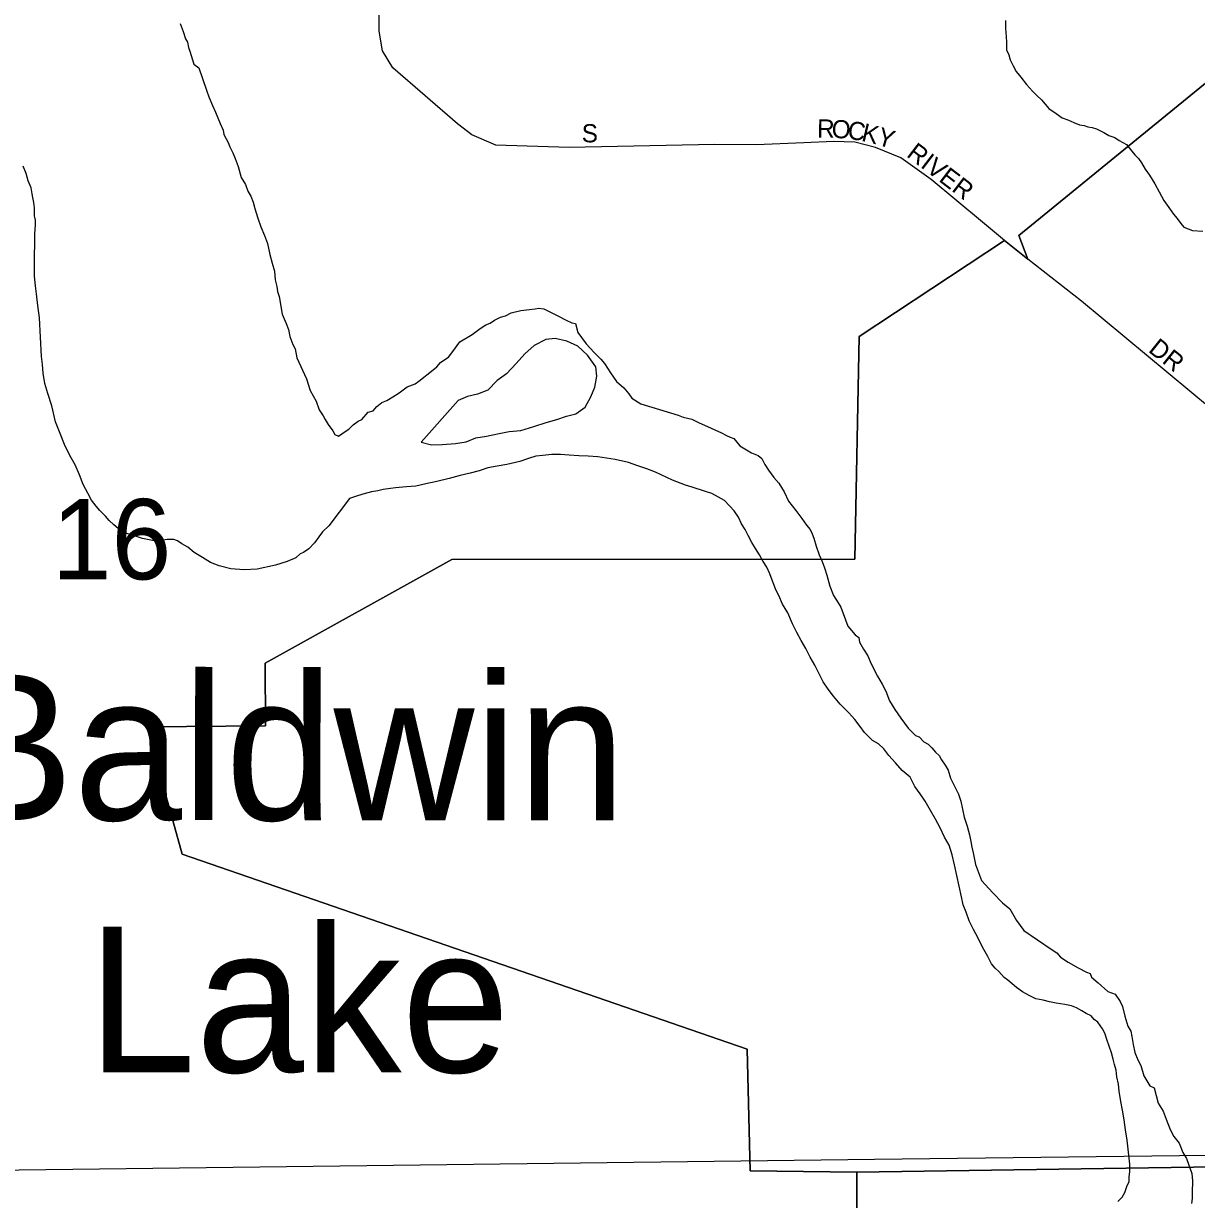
# Model space of a CAD drawing. Extents: x 2010165 to 2382125, y 1060529 to 1407316.
# Drawn here: x 2145137 to 2148360, y 1221171 to 1224404 of the extents above; entities that cross this region are included whole.
import ezdxf

# ---------------------------------------------------------------- set-up
doc = ezdxf.new("R2010")
doc.units = 0
for name, color, linetype in [('GM_X_City_Street', 7, 'Continuous'), ('GM_X_City_Street_Text', 7, 'Continuous'), ('GM_X_Corporation', 7, 'Continuous'), ('GM_X_Major_River', 7, 'Continuous'), ('GM_X_Minor_Lake_Text', 7, 'Continuous'), ('GM_X_Minor_River', 7, 'Continuous'), ('GM_X_Minor_River_Text', 7, 'Continuous'), ('GM_X_Section', 7, 'Continuous'), ('GM_X_Section_Text', 7, 'Continuous')]:
    doc.layers.add(name, color=color, linetype=linetype)

msp = doc.modelspace()

# ---------------------------------------------------------------- linework, layer by layer
at = {"layer": 'GM_X_City_Street'}
for points in [[(2147771.7, 1223857.6), (2147631.2, 1223974.9), (2147547.3, 1224035.1), (2147477.7, 1224063.5), (2147420.8, 1224077.8), (2147362.2, 1224079.3), (2147281.5, 1224076.2), (2147149.8, 1224070.3), (2147035.8, 1224071.2), (2146636, 1224063.5), (2146435, 1224069.9), (2146368.5, 1224098.3), (2146329, 1224128.4), (2146151.8, 1224281.9), (2146123.3, 1224329.3), (2146113.8, 1224383.1), (2146115.4, 1224800.9), (2146107.5, 1225125.2), (2146102.7, 1225683.8), (2146099.5, 1225758.1), (2146090.1, 1225826.2), (2146034.9, 1226118.8)], [(2148520, 1223244.9), (2148044.2, 1223641.1), (2147897, 1223756.5), (2147832.2, 1223807.2), (2147771.7, 1223857.6)]]:
    msp.add_lwpolyline(points, dxfattribs=at)
at = {"layer": 'GM_X_Corporation'}
for points in [[(2148518.6, 1224348.8), (2147871.9, 1223821.2), (2147897, 1223756.6), (2147832.2, 1223807.2), (2147433.5, 1223543.6), (2147420.8, 1222931.5), (2146313.5, 1222930.5), (2145801.1, 1222645.7), (2145801.8, 1222473.2), (2145475.4, 1222470.1), (2145572.8, 1222120.5), (2147124.9, 1221584.6), (2147133.9, 1221249.7), (2147426.3, 1221246.2), (2147423.5, 1218928.8)], [(2151804.7, 1221311.6), (2147426.3, 1221246.2), (2147133.9, 1221249.7), (2147124.9, 1221584.6), (2145572.8, 1222120.5), (2145475.4, 1222470.1), (2145801.8, 1222473.2), (2145801.1, 1222645.7), (2146313.5, 1222930.5), (2147420.8, 1222931.5), (2147433.5, 1223543.6), (2147832.2, 1223807.2), (2147897, 1223756.6), (2147871.9, 1223821.2), (2148518.6, 1224348.8)], [(2147423.5, 1218928.8), (2147426.3, 1221246.2), (2151804.7, 1221311.6), (2152701.8, 1221309.3), (2153236.4, 1221311.5), (2153786.8, 1221330), (2154189.1, 1221338.2), (2155059.4, 1221364.3), (2155838.4, 1221371.7), (2159035.7, 1221398.8), (2160539.4, 1221412.4), (2164895.8, 1221436.7), (2164832.8, 1218637)]]:
    msp.add_lwpolyline(points, dxfattribs=at)
at = {"layer": 'GM_X_Major_River'}
for points in [[(2145567, 1224404.4), (2145575.3, 1224382.4), (2145581.6, 1224362.4), (2145587.7, 1224352.5), (2145589.9, 1224338.4), (2145594.1, 1224328.5), (2145604.6, 1224292.5), (2145618.7, 1224282.6), (2145639.6, 1224220.7), (2145645.8, 1224202.7), (2145656.1, 1224178.7), (2145664.4, 1224160.8), (2145670.6, 1224144.8), (2145676.8, 1224128.8), (2145685.1, 1224110.9), (2145687.2, 1224098.9), (2145693.4, 1224086.9), (2145699.5, 1224076.9), (2145703.7, 1224064.9), (2145711.9, 1224049), (2145718.1, 1224033), (2145726.5, 1224011.1), (2145734.9, 1223981.1), (2145747.1, 1223961.1), (2145753.4, 1223943.2), (2145761.6, 1223929.2), (2145767.8, 1223913.2), (2145772, 1223895.2), (2145780.4, 1223869.3), (2145788.7, 1223845.3), (2145799.1, 1223821.3), (2145807.4, 1223799.4), (2145813.8, 1223769.3), (2145820.1, 1223745.3), (2145826.4, 1223723.3), (2145828.7, 1223699.3), (2145832.9, 1223681.3), (2145835.1, 1223667.3), (2145839.3, 1223653.3), (2145848, 1223605.2), (2145858.3, 1223579.3), (2145864.6, 1223563.3), (2145868.8, 1223543.3), (2145877.1, 1223521.3), (2145883.3, 1223509.3), (2145887.6, 1223485.3), (2145914.4, 1223427.5), (2145924.8, 1223395.5), (2145941.3, 1223365.6), (2145949.6, 1223341.6), (2145959.8, 1223325.7), (2145966, 1223315.7), (2145974.2, 1223301.8), (2145986.4, 1223283.9), (2145992.6, 1223273.9), (2146002.6, 1223270), (2146020.5, 1223282.3), (2146030.4, 1223288.4), (2146042.3, 1223300.6), (2146056.2, 1223310.8), (2146066.1, 1223315), (2146083.9, 1223335.2), (2146097.9, 1223339.4), (2146107.7, 1223351.6), (2146121.6, 1223361.8), (2146135.6, 1223368), (2146151.5, 1223378.2), (2146169.4, 1223388.5), (2146191.2, 1223404.8), (2146213.1, 1223413.1), (2146223, 1223421.2)], [(2145180.9, 1223595), (2145176.5, 1223629.1), (2145172.1, 1223661.1), (2145169.8, 1223683.2), (2145167.4, 1223709.2), (2145167, 1223739.3), (2145166.7, 1223767.4), (2145168.3, 1223797.5), (2145167.9, 1223825.6), (2145169.6, 1223849.7), (2145169.4, 1223863.8), (2145167.2, 1223875.8), (2145167.1, 1223887.8), (2145166.9, 1223897.8), (2145164.8, 1223911.9), (2145162.6, 1223925.9), (2145160.4, 1223935.9), (2145158.2, 1223951.9), (2145149.9, 1223971.9), (2145143.7, 1223991.9), (2145135.4, 1224011.8)], [(2146223, 1223421.2), (2146262.7, 1223451.8), (2146272.6, 1223460), (2146282.5, 1223472.1), (2146294.4, 1223480.3), (2146304.3, 1223486.4), (2146316.1, 1223502.6), (2146335.8, 1223528.9), (2146369.6, 1223549.4), (2146391.4, 1223565.8), (2146407.3, 1223576), (2146419.3, 1223580.1), (2146431.2, 1223588.3), (2146447.1, 1223596.5), (2146461.1, 1223600.7), (2146477, 1223608.9), (2146503, 1223615.3), (2146527, 1223617.6), (2146543, 1223619.8), (2146553, 1223621.9), (2146567, 1223620.1), (2146581.2, 1223612.2), (2146605.4, 1223600.5), (2146627.6, 1223588.7), (2146643.7, 1223580.9), (2146653.7, 1223579), (2146660.1, 1223555), (2146682.5, 1223523.2), (2146704.9, 1223499.4), (2146723.1, 1223481.5), (2146733.3, 1223469.6), (2146749.7, 1223443.7), (2146766, 1223419.9), (2146786.3, 1223402.1), (2146800.5, 1223386.2), (2146808.7, 1223374.2), (2146832.9, 1223358.5), (2146935.5, 1223327.6), (2146949.6, 1223321.8), (2146973.7, 1223316.1), (2146993.9, 1223306.3), (2147016.1, 1223296.5), (2147036.2, 1223286.7), (2147054.4, 1223278.9), (2147068.5, 1223271.1), (2147078.6, 1223267.2), (2147088.6, 1223263.3), (2147104.9, 1223243.4), (2147137.2, 1223223.8), (2147155.4, 1223216), (2147165.5, 1223208.1), (2147173.7, 1223192.1), (2147183.9, 1223176.2), (2147198.2, 1223156.3), (2147212.4, 1223140.4), (2147226.8, 1223116.5), (2147239.1, 1223090.6), (2147259.5, 1223064.8), (2147275.8, 1223042.9), (2147288.1, 1223025), (2147298.3, 1223013.1), (2147304.4, 1223001.1), (2147308.6, 1222989.1), (2147314.9, 1222967.1), (2147323.2, 1222943.1), (2147331.5, 1222925.2), (2147337.7, 1222907.2), (2147344, 1222887.2), (2147352.4, 1222857.2), (2147362.7, 1222831.3), (2147375, 1222811.3), (2147383.2, 1222799.4), (2147401.9, 1222747.5), (2147422.3, 1222723.6), (2147432.4, 1222715.7), (2147434.5, 1222703.7), (2147444.8, 1222683.8), (2147457.1, 1222665.9), (2147465.4, 1222645.9), (2147483.9, 1222610), (2147496.2, 1222588.1), (2147506.4, 1222568.2), (2147516.8, 1222542.2), (2147531.1, 1222518.3), (2147547.5, 1222494.4), (2147567.9, 1222466.6), (2147588.2, 1222446.8), (2147598.2, 1222442.9), (2147610.4, 1222429), (2147622.5, 1222423.1), (2147632.7, 1222413.2), (2147642.9, 1222401.3), (2147653, 1222391.4), (2147659.2, 1222379.4), (2147669.4, 1222365.5), (2147677.6, 1222351.6), (2147683.9, 1222329.6), (2147696.2, 1222305.6), (2147706.5, 1222285.7), (2147712.8, 1222265.7), (2147721.3, 1222221.7)], [(2147169.2, 1222925.2), (2147158.9, 1222943.1), (2147148.7, 1222961.1), (2147138.4, 1222977), (2147128.2, 1222996.9), (2147119.9, 1223012.9), (2147109.7, 1223028.8), (2147101.5, 1223046.8), (2147089.2, 1223064.7), (2147062.8, 1223092.4), (2147046.7, 1223102.3), (2147028.5, 1223112.1), (2147010.4, 1223117.9), (2146974.2, 1223129.5), (2146956.1, 1223135.3), (2146919.8, 1223148.9), (2146873.5, 1223170.4), (2146849.3, 1223180.1), (2146825.1, 1223187.8), (2146799, 1223197.6), (2146762.8, 1223205.1), (2146738.7, 1223208.8), (2146714.6, 1223212.6), (2146688.6, 1223214.2), (2146662.5, 1223215.9), (2146636.4, 1223217.6), (2146612.4, 1223219.3), (2146588.3, 1223219), (2146564.3, 1223216.7), (2146544.3, 1223214.5), (2146524.3, 1223208.2), (2146500.4, 1223199.9), (2146464.5, 1223191.4), (2146438.5, 1223187.1), (2146412.5, 1223182.8), (2146388.6, 1223174.4), (2146364.6, 1223168.1), (2146336.6, 1223161.8), (2146306.7, 1223153.4), (2146272.7, 1223144.9), (2146242.8, 1223138.6), (2146214.8, 1223132.2), (2146188.8, 1223129.9), (2146158.8, 1223127.5), (2146144.8, 1223125.3), (2146124.8, 1223123.1), (2146110.8, 1223118.9), (2146092.8, 1223116.6), (2146068.8, 1223110.3), (2146048.9, 1223104.1), (2146032.9, 1223097.8), (2145975.8, 1223022.9), (2145958, 1223006.6), (2145948.2, 1222992.5), (2145936.4, 1222976.3), (2145920.5, 1222960), (2145906.6, 1222949.8), (2145896.7, 1222945.7), (2145884.8, 1222935.5), (2145860.9, 1222925.2), (2145829, 1222914.8), (2145779, 1222904.1), (2145743, 1222901.7), (2145706.9, 1222905.2), (2145674.7, 1222912.9), (2145650.5, 1222922.6), (2145628.3, 1222936.4), (2145606.1, 1222950.1), (2145587.9, 1222964), (2145571.7, 1222973.8), (2145559.6, 1222981.7), (2145549.5, 1222985.6), (2145531.5, 1222985.3), (2145515.5, 1222983.1), (2145491.5, 1222982.9), (2145463.4, 1222988.5), (2145439.2, 1222996.3), (2145421.1, 1223002.1), (2145409, 1223007.9), (2145396.9, 1223015.8), (2145384.7, 1223025.7), (2145372.6, 1223037.6), (2145362.4, 1223049.5), (2145346.1, 1223065.3), (2145336, 1223077.3), (2145323.7, 1223093.2), (2145313.5, 1223113.1), (2145301.1, 1223137), (2145290.8, 1223163), (2145278.4, 1223190.9), (2145264, 1223216.8), (2145249.6, 1223246.8), (2145237.2, 1223276.7), (2145224.8, 1223308.6), (2145214.2, 1223352.7), (2145203.7, 1223386.6), (2145195.3, 1223414.6), (2145190.9, 1223442.7), (2145188.6, 1223466.7), (2145186.3, 1223488.8), (2145180.9, 1223595)], [(2146331, 1223367.9), (2146229.4, 1223253.3)], [(2148143.9, 1221165.4), (2148155.7, 1221177.6), (2148163.6, 1221189.8), (2148169.3, 1221209.9), (2148175.2, 1221220), (2148175.1, 1221232), (2148176.9, 1221248.1), (2148176.6, 1221268.2), (2148169.7, 1221334.3), (2148165.3, 1221362.3), (2148161, 1221390.4), (2148156.6, 1221416.4), (2148152.3, 1221440.4), (2148147.9, 1221468.5), (2148145.7, 1221488.5), (2148141.4, 1221508.5), (2148139.2, 1221526.6), (2148134.9, 1221542.6), (2148130.8, 1221556.5), (2148126.5, 1221574.5), (2148120.3, 1221592.5), (2148114, 1221610.5), (2148107.8, 1221628.5), (2148101.6, 1221640.5), (2148089.3, 1221658.4), (2148079.2, 1221666.3), (2148071.1, 1221676.2), (2148057, 1221682.1), (2148044.9, 1221689.9), (2148030.7, 1221697.8), (2148016.6, 1221703.6), (2147998.6, 1221707.4), (2147974.5, 1221711.1), (2147956.4, 1221714.9), (2147938.3, 1221718.7), (2147918.2, 1221722.5), (2147900.1, 1221732.3), (2147881.9, 1221742.1), (2147865.7, 1221753.9), (2147853.6, 1221763.8), (2147841.4, 1221773.7), (2147831.3, 1221781.6), (2147817.1, 1221797.5), (2147806.9, 1221807.4), (2147796.7, 1221819.3), (2147786.4, 1221839.2), (2147772.1, 1221865.1), (2147759.8, 1221889.1), (2147747.4, 1221913), (2147735.1, 1221936.9), (2147726.8, 1221960.9), (2147718.5, 1221980.9), (2147714.2, 1222002.9), (2147695, 1222090.9), (2147688.6, 1222118.9), (2147680.3, 1222144.9), (2147668, 1222166.8), (2147655.6, 1222192.8), (2147643.3, 1222216.7), (2147628.9, 1222240.6), (2147614.6, 1222266.5), (2147600.3, 1222286.4), (2147586, 1222306.3), (2147573.6, 1222332.2), (2147551.4, 1222350), (2147533.1, 1222371.9), (2147514.8, 1222391.7), (2147500.5, 1222409.6), (2147486.3, 1222423.5), (2147470.1, 1222433.3), (2147460, 1222443.2), (2147447.8, 1222455.1), (2147435.6, 1222471), (2147421.3, 1222490.9), (2147405, 1222508.7), (2147380.7, 1222532.5), (2147362.4, 1222554.4), (2147348.1, 1222574.3), (2147333.8, 1222594.1), (2147323.5, 1222616.1), (2147311.2, 1222640), (2147298.9, 1222661.9), (2147286.5, 1222685.9), (2147274.2, 1222707.8), (2147261.9, 1222729.7), (2147249.6, 1222753.6), (2147237.2, 1222783.6), (2147222.8, 1222807.5), (2147212.5, 1222831.4), (2147204.3, 1222847.4), (2147200.1, 1222857.4), (2147193.9, 1222873.3), (2147187.7, 1222891.3), (2147179.4, 1222909.3), (2147169.2, 1222925.2)], [(2147721.3, 1222221.7), (2147729.7, 1222197.7), (2147733.9, 1222183.7), (2147736, 1222173.7), (2147740.2, 1222155.7), (2147742.4, 1222139.7), (2147746.7, 1222123.7), (2147753.1, 1222091.6), (2147769.7, 1222047.7), (2147800.2, 1222014), (2147826.6, 1221986.2), (2147846.8, 1221970.4), (2147865.3, 1221938.5), (2147885.7, 1221910.7), (2147960.5, 1221859.4), (2147976.6, 1221849.6), (2147986.8, 1221837.7), (2148007, 1221823.9), (2148035.3, 1221808.2), (2148057.5, 1221796.4), (2148067.6, 1221792.5), (2148071.7, 1221782.5), (2148089.9, 1221766.7), (2148116.3, 1221743), (2148136.4, 1221735.2), (2148150.7, 1221715.3), (2148156.9, 1221701.3), (2148163.3, 1221675.3), (2148171.6, 1221647.3), (2148179.8, 1221633.4), (2148182, 1221619.4), (2148186.3, 1221597.3), (2148190.6, 1221575.3), (2148198.9, 1221555.4), (2148207.1, 1221539.4), (2148215.5, 1221511.4), (2148231.9, 1221483.5), (2148244, 1221477.7), (2148254.5, 1221435.7), (2148268.9, 1221413.8), (2148277.2, 1221391.8), (2148287.5, 1221363.8), (2148297.8, 1221343.9), (2148312.1, 1221326), (2148322.4, 1221300.1), (2148332.7, 1221284.1), (2148347.2, 1221242.2), (2148349.5, 1221222.1), (2148347.9, 1221190), (2148348.1, 1221174), (2148346.3, 1221159.9)]]:
    msp.add_lwpolyline(points, dxfattribs=at)
at = {"layer": 'GM_X_Minor_River'}
msp.add_lwpolyline([(2147834.9, 1224412.1), (2147835.2, 1224390.1), (2147837.5, 1224368), (2147837.7, 1224352), (2147838, 1224331.9), (2147844.2, 1224318), (2147848.4, 1224304), (2147856.6, 1224288), (2147864.8, 1224272.1), (2147877, 1224256.2), (2147893.3, 1224236.3), (2147909.6, 1224218.4), (2147921.8, 1224206.6), (2147933.9, 1224194.7), (2147944.1, 1224182.7), (2147954.3, 1224170.8), (2147974.5, 1224157), (2147990.7, 1224145.2), (2148006.8, 1224139.4), (2148022.9, 1224131.6), (2148039, 1224125.7), (2148051.1, 1224123.9), (2148061.1, 1224120), (2148073.2, 1224118.1), (2148085.2, 1224114.2), (2148105.4, 1224104.5), (2148119.5, 1224096.6), (2148135.6, 1224090.8), (2148147.8, 1224082.9), (2148157.9, 1224077), (2148168, 1224071.1), (2148182.2, 1224053.2), (2148190.4, 1224043.3), (2148200.5, 1224033.4), (2148208.7, 1224021.5), (2148218.9, 1224003.5), (2148231.2, 1223987.6), (2148245.5, 1223963.7), (2148257.8, 1223941.8), (2148270.1, 1223917.9), (2148284.4, 1223898), (2148296.7, 1223880.1), (2148306.9, 1223868.2), (2148317.1, 1223854.2), (2148325.2, 1223844.3), (2148349.4, 1223834.6), (2148377.4, 1223832.9)], dxfattribs=at)
at = {"layer": 'GM_X_Minor_River_Text'}
msp.add_lwpolyline([(2146229.4, 1223253.3), (2146257.6, 1223245.9), (2146287.6, 1223246.6), (2146323.7, 1223249.4), (2146353.6, 1223254), (2146379.4, 1223264.6), (2146409.4, 1223269.3), (2146439.3, 1223276), (2146471.2, 1223282.7), (2146503.2, 1223285.4), (2146539, 1223296.2), (2146572.8, 1223307), (2146602.7, 1223315.7), (2146628.6, 1223324.3), (2146654.5, 1223330.8), (2146680.1, 1223349.5), (2146695.5, 1223377.9), (2146706.9, 1223404.2), (2146712.3, 1223434.4), (2146709.7, 1223460.5), (2146686.9, 1223492.1), (2146660.3, 1223517.5), (2146629.9, 1223530.9), (2146597.7, 1223538.2), (2146571.7, 1223535.7), (2146540, 1223518.9), (2146514.5, 1223496.3), (2146491, 1223469.7), (2146463.6, 1223441), (2146438, 1223422.4), (2146412.5, 1223395.8), (2146384.7, 1223385.1), (2146356.8, 1223378.5), (2146331, 1223367.9)], dxfattribs=at)
at = {"layer": 'GM_X_Section'}
msp.add_lwpolyline([(2148600.9, 1224775.6), (2148465.7, 1221292.7), (2147475.7, 1221281.4), (2145050.4, 1221250.4), (2143284.1, 1221252.1), (2143408.8, 1224809.4)], close=True, dxfattribs=at)

# ---------------------------------------------------------------- texts
at = {"layer": 'GM_X_City_Street_Text'}
for s, rotation, p in [('S', 0, (2146670.7, 1224077.4)), ('R', 359.49, (2147317.4, 1224090.6)), ('O', 356.3037, (2147356.2, 1224090.3)), ('C', 351.468, (2147399, 1224087.6)), ('K', 346.7007, (2147437.1, 1224081.9)), ('Y', 343.4452, (2147479.2, 1224072)), ('RIVER', 322.5939, (2147560.8, 1224040.2)), ('DR', 321.3455, (2148225.3, 1223503.3))]:
    msp.add_text(s, height=50, rotation=rotation, dxfattribs=at).set_placement(p)
at = {"layer": 'GM_X_Minor_Lake_Text'}
for s, height, p in [('Baldwin', 400.23, (2144917.7, 1222214.1)), ('Lake', 400.22, (2145312.5, 1221520.9))]:
    msp.add_text(s, height=height, rotation=359.9852, dxfattribs=at).set_placement(p)
at = {"layer": 'GM_X_Section_Text'}
msp.add_text('16', height=221, rotation=0, dxfattribs=at).set_placement((2145214.3, 1222875.9))

doc.saveas('drawing.dxf')
